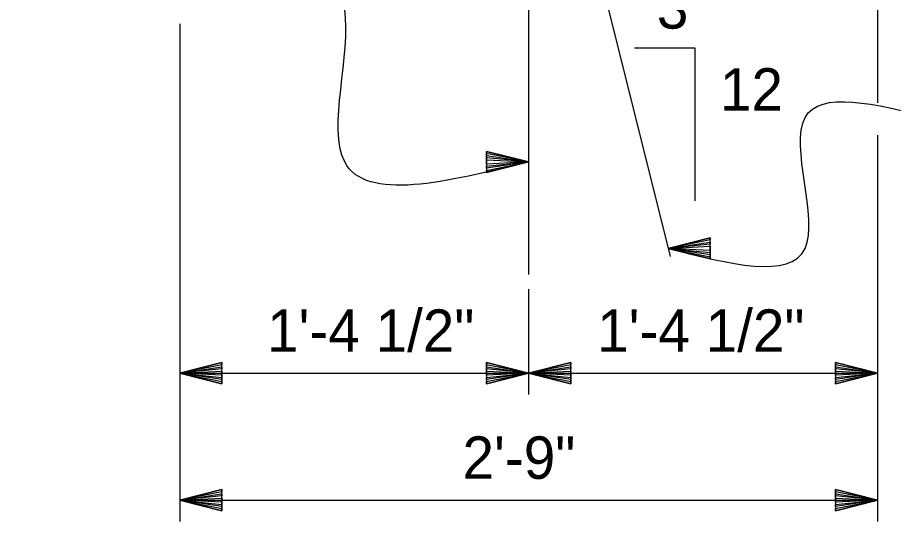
# Model space of a CAD drawing. Extents: x -41 to 251, y -169 to 237.
# Drawn here: x 45.14 to 51.05, y -163.27 to -159.88 of the extents above; entities that cross this region are included whole.
import ezdxf

# ---------------------------------------------------------------- set-up
doc = ezdxf.new("R2010")
doc.units = 0
for name, color, linetype in [('Arrowhead Terminators CELL', 7, 'Continuous'), ('Dimension Lines', 7, 'Continuous'), ('Dimension Lines CELL', 7, 'Continuous'), ('Mis Center Lines CELL', 7, 'Continuous'), ('Text', 7, 'Continuous'), ('Text CELL', 7, 'Continuous')]:
    doc.layers.add(name, color=color, linetype=linetype)

msp = doc.modelspace()

# ---------------------------------------------------------------- linework, layer by layer
at = {"layer": 'Arrowhead Terminators CELL'}
for points in [[(48.3038, -160.85), (48.3038, -160.8357), (48.5885, -160.85), (48.3038, -160.8216), (48.3038, -160.8072), (48.5885, -160.85), (48.3038, -160.7932), (48.3038, -160.7788), (48.5885, -160.85), (48.3038, -160.9211), (48.3038, -160.9069), (48.5885, -160.85), (48.3038, -160.8927), (48.3038, -160.8784), (48.5885, -160.85), (48.3038, -160.8643), (48.3038, -160.7788), (48.3038, -160.9211), (48.5885, -160.85), (48.3038, -160.7788)], [(49.8138, -161.433), (49.8138, -161.4472), (49.5291, -161.433), (49.8138, -161.4614), (49.8138, -161.4757), (49.5291, -161.433), (49.8138, -161.4898), (49.8138, -161.5042), (49.5291, -161.433), (49.8138, -161.3619), (49.8138, -161.3761), (49.5291, -161.433), (49.8138, -161.3903), (49.8138, -161.4045), (49.5291, -161.433), (49.8138, -161.4187), (49.8138, -161.5042), (49.8138, -161.3619), (49.5291, -161.433), (49.8138, -161.5042)], [(46.519, -162.2738), (46.519, -162.2881), (46.2344, -162.2738), (46.519, -162.3023), (46.519, -162.3166), (46.2344, -162.2738), (46.519, -162.3307), (46.519, -162.345), (46.2344, -162.2738), (46.519, -162.2027), (46.519, -162.217), (46.2344, -162.2738), (46.519, -162.2311), (46.519, -162.2454), (46.2344, -162.2738), (46.519, -162.2596), (46.519, -162.345), (46.519, -162.2027), (46.2344, -162.2738), (46.519, -162.345)], [(48.3038, -162.2738), (48.3038, -162.2596), (48.5885, -162.2738), (48.3038, -162.2454), (48.3038, -162.2311), (48.5885, -162.2738), (48.3038, -162.217), (48.3038, -162.2027), (48.5885, -162.2738), (48.3038, -162.345), (48.3038, -162.3307), (48.5885, -162.2738), (48.3038, -162.3166), (48.3038, -162.3023), (48.5885, -162.2738), (48.3038, -162.2881), (48.3038, -162.2027), (48.3038, -162.345), (48.5885, -162.2738), (48.3038, -162.2027)], [(48.8731, -162.2738), (48.8731, -162.2881), (48.5885, -162.2738), (48.8731, -162.3023), (48.8731, -162.3166), (48.5885, -162.2738), (48.8731, -162.3307), (48.8731, -162.345), (48.5885, -162.2738), (48.8731, -162.2027), (48.8731, -162.217), (48.5885, -162.2738), (48.8731, -162.2311), (48.8731, -162.2454), (48.5885, -162.2738), (48.8731, -162.2596), (48.8731, -162.345), (48.8731, -162.2027), (48.5885, -162.2738), (48.8731, -162.345)], [(50.6579, -162.2738), (50.6579, -162.2596), (50.9425, -162.2738), (50.6579, -162.2454), (50.6579, -162.2311), (50.9425, -162.2738), (50.6579, -162.217), (50.6579, -162.2027), (50.9425, -162.2738), (50.6579, -162.345), (50.6579, -162.3307), (50.9425, -162.2738), (50.6579, -162.3166), (50.6579, -162.3023), (50.9425, -162.2738), (50.6579, -162.2881), (50.6579, -162.2027), (50.6579, -162.345), (50.9425, -162.2738), (50.6579, -162.2027)], [(46.519, -163.13), (46.519, -163.1442), (46.2344, -163.13), (46.519, -163.1584), (46.519, -163.1727), (46.2344, -163.13), (46.519, -163.1869), (46.519, -163.2012), (46.2344, -163.13), (46.519, -163.0588), (46.519, -163.073), (46.2344, -163.13), (46.519, -163.0873), (46.519, -163.1015), (46.2344, -163.13), (46.519, -163.1157), (46.519, -163.2012), (46.519, -163.0588), (46.2344, -163.13), (46.519, -163.2012)], [(50.6579, -163.13), (50.6579, -163.1157), (50.9425, -163.13), (50.6579, -163.1015), (50.6579, -163.0873), (50.9425, -163.13), (50.6579, -163.073), (50.6579, -163.0588), (50.9425, -163.13), (50.6579, -163.2012), (50.6579, -163.1869), (50.9425, -163.13), (50.6579, -163.1727), (50.6579, -163.1584), (50.9425, -163.13), (50.6579, -163.1442), (50.6579, -163.0588), (50.6579, -163.2012), (50.9425, -163.13), (50.6579, -163.0588)]]:
    msp.add_lwpolyline(points, dxfattribs=at)
at = {"layer": 'Dimension Lines'}
msp.add_lwpolyline([(49.3037, -160.08), (49.7099, -160.08), (49.7099, -161.1132)], dxfattribs=at)
at = {"layer": 'Dimension Lines CELL'}
for p, q in [((50.9425, -157.8079), (50.9425, -160.4506)), ((46.2344, -159.9179), (46.2344, -163.2738)), ((50.9425, -160.6703), (50.9425, -163.2738)), ((46.2344, -162.2738), (48.5885, -162.2738)), ((48.5885, -162.2738), (50.9425, -162.2738)), ((46.2344, -163.13), (50.9425, -163.13))]:
    msp.add_line(p, q, dxfattribs=at)
for points in [[(50.7286, -157.4106), (51.7388, -157.4106), (51.7388, -159.7301), (52.8924, -159.7301)], [(48.5885, -160.85), (47.3476, -160.85), (47.3476, -159.8215), (45.1405, -159.8215)], [(49.5291, -161.433), (50.4532, -161.433), (50.4532, -160.5505), (51.3019, -160.5505)]]:
    msp.add_spline(points, degree=3, dxfattribs=at)
at = {"layer": 'Mis Center Lines CELL'}
for p, q in [((48.5885, -158.6169), (48.5885, -161.4874)), ((48.8666, -158.7765), (49.5441, -161.4874))]:
    msp.add_line(p, q, dxfattribs=at)
at = {"layer": 'Text'}
for p, q in [((48.5885, -161.2694), (48.5885, -161.6089)), ((48.5885, -161.7088), (48.5885, -162.4177))]:
    msp.add_line(p, q, dxfattribs=at)

# ---------------------------------------------------------------- texts
at = {"layer": 'Text CELL'}
for s, height, p in [('3', 0.2859, (49.4535, -159.9513)), ('12', 0.28588, (49.879, -160.5041)), ('1\'-4 1/2"', 0.28588, (46.8239, -162.1301)), ('1\'-4 1/2"', 0.28588, (49.0507, -162.1301)), ('2\'-9"', 0.28588, (48.1426, -162.9862))]:
    msp.add_text(s, height=height, dxfattribs=at).set_placement(p)

doc.saveas('drawing.dxf')
